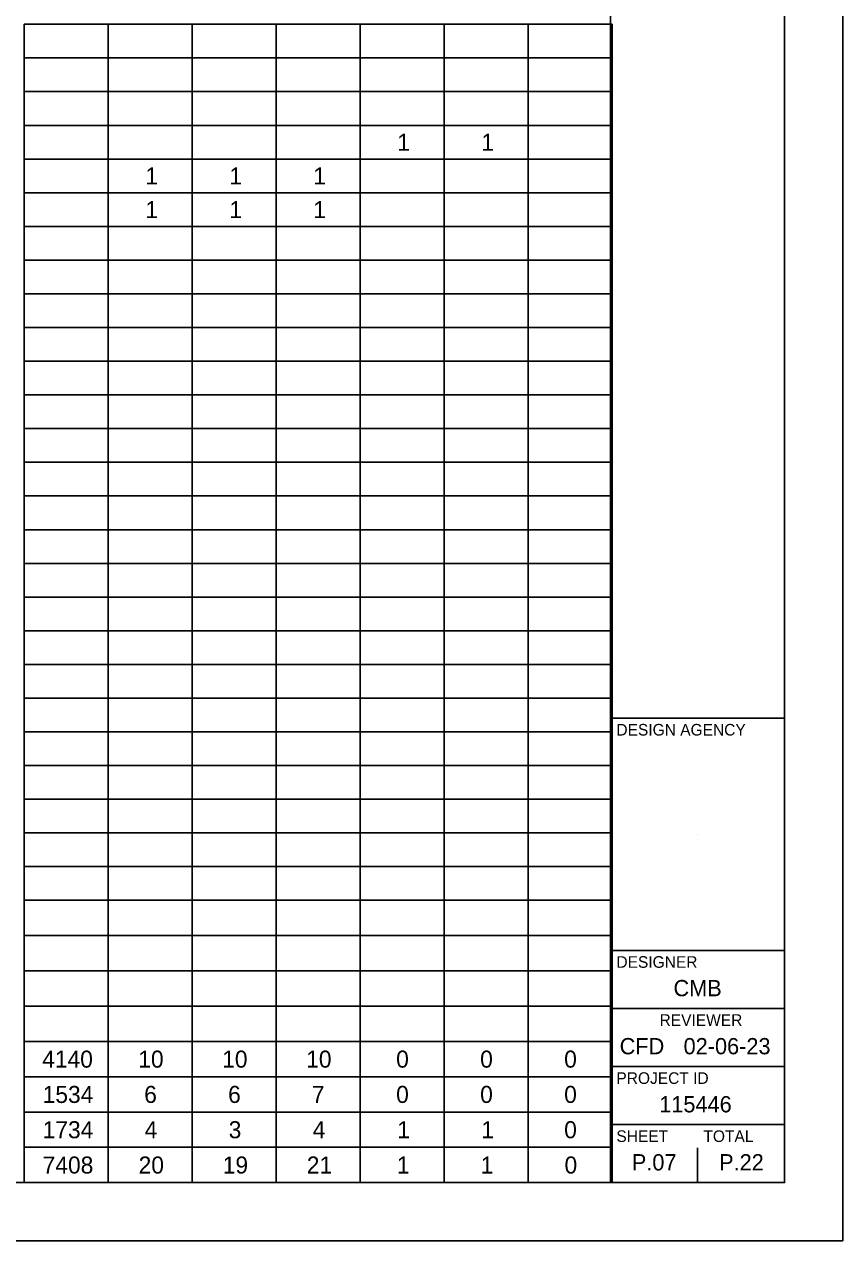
# Model space of a CAD drawing. Extents: x 0 to 34, y 0 to 22.
# Drawn here: x 26.95 to 34, y 0 to 10.47 of the extents above; entities that cross this region are included whole.
import ezdxf

# ---------------------------------------------------------------- set-up
doc = ezdxf.new("R2010")
doc.units = 0
for name, color, linetype in [('Default', 7, 'Continuous'), ('SH_Border', 7, 'Continuous'), ('SH_Cut_Line', 7, 'Continuous'), ('SH_Data', 7, 'Continuous')]:
    doc.layers.add(name, color=color, linetype=linetype)

msp = doc.modelspace()

# ---------------------------------------------------------------- linework, layer by layer
at = {"layer": 'Default'}
for p, q in [((26.948, 10.475), (27.671, 10.475)), ((26.948, 10.475), (26.948, 10.185)), ((27.671, 10.475), (29.842, 10.475)), ((27.671, 10.475), (27.671, 10.185)), ((28.395, 10.475), (28.395, 10.185)), ((29.119, 10.475), (29.119, 10.185)), ((29.842, 10.475), (30.566, 10.475)), ((29.842, 10.475), (29.842, 10.185)), ((30.566, 10.475), (31.289, 10.475)), ((30.566, 10.475), (30.566, 10.185)), ((31.289, 10.475), (32.013, 10.475)), ((31.289, 10.475), (31.289, 10.185)), ((32.013, 10.475), (32.013, 10.185)), ((26.948, 10.185), (27.671, 10.185)), ((26.948, 10.185), (26.948, 9.895)), ((27.671, 10.185), (29.842, 10.185)), ((27.671, 10.185), (27.671, 9.895)), ((28.395, 10.185), (28.395, 9.895)), ((29.119, 10.185), (29.119, 9.895)), ((29.842, 10.185), (30.566, 10.185)), ((29.842, 10.185), (29.842, 9.895)), ((30.566, 10.185), (31.289, 10.185)), ((30.566, 10.185), (30.566, 9.895)), ((31.289, 10.185), (32.013, 10.185)), ((31.289, 10.185), (31.289, 9.895)), ((32.013, 10.185), (32.013, 9.895)), ((26.948, 9.895), (27.671, 9.895)), ((26.948, 9.895), (26.948, 9.604)), ((27.671, 9.895), (29.842, 9.895)), ((27.671, 9.895), (27.671, 9.604)), ((28.395, 9.895), (28.395, 9.604)), ((29.119, 9.895), (29.119, 9.604)), ((29.842, 9.895), (30.566, 9.895)), ((29.842, 9.895), (29.842, 9.604)), ((30.566, 9.895), (31.289, 9.895)), ((30.566, 9.895), (30.566, 9.604)), ((31.289, 9.895), (32.013, 9.895)), ((31.289, 9.895), (31.289, 9.604)), ((32.013, 9.895), (32.013, 9.604)), ((26.948, 9.604), (27.671, 9.604)), ((26.948, 9.604), (26.948, 9.314)), ((27.671, 9.604), (29.842, 9.604)), ((27.671, 9.604), (27.671, 9.314)), ((28.395, 9.604), (28.395, 9.314)), ((29.119, 9.604), (29.119, 9.314)), ((29.842, 9.604), (30.566, 9.604)), ((29.842, 9.604), (29.842, 9.314)), ((30.566, 9.604), (31.289, 9.604)), ((30.566, 9.604), (30.566, 9.314)), ((31.289, 9.604), (32.013, 9.604)), ((31.289, 9.604), (31.289, 9.314)), ((32.013, 9.604), (32.013, 9.314)), ((26.948, 9.314), (27.671, 9.314)), ((26.948, 9.314), (26.948, 9.024)), ((27.671, 9.314), (29.842, 9.314)), ((27.671, 9.314), (27.671, 9.024)), ((28.395, 9.314), (28.395, 9.024)), ((29.119, 9.314), (29.119, 9.024)), ((29.842, 9.314), (30.566, 9.314)), ((29.842, 9.314), (29.842, 9.024)), ((30.566, 9.314), (31.289, 9.314)), ((30.566, 9.314), (30.566, 9.024)), ((31.289, 9.314), (32.013, 9.314)), ((31.289, 9.314), (31.289, 9.024)), ((32.013, 9.314), (32.013, 9.024)), ((26.948, 9.024), (27.671, 9.024)), ((26.948, 9.024), (26.948, 8.734)), ((27.671, 9.024), (29.842, 9.024)), ((27.671, 9.024), (27.671, 8.734)), ((28.395, 9.024), (28.395, 8.734)), ((29.119, 9.024), (29.119, 8.734)), ((29.842, 9.024), (30.566, 9.024)), ((29.842, 9.024), (29.842, 8.734)), ((30.566, 9.024), (31.289, 9.024)), ((30.566, 9.024), (30.566, 8.734)), ((31.289, 9.024), (32.013, 9.024)), ((31.289, 9.024), (31.289, 8.734)), ((32.013, 9.024), (32.013, 8.734)), ((26.948, 8.734), (27.671, 8.734)), ((26.948, 8.734), (26.948, 8.444)), ((27.671, 8.734), (29.842, 8.734)), ((27.671, 8.734), (27.671, 8.444)), ((28.395, 8.734), (28.395, 8.444)), ((29.119, 8.734), (29.119, 8.444)), ((29.842, 8.734), (30.566, 8.734)), ((29.842, 8.734), (29.842, 8.444)), ((30.566, 8.734), (31.289, 8.734)), ((30.566, 8.734), (30.566, 8.444)), ((31.289, 8.734), (32.013, 8.734)), ((31.289, 8.734), (31.289, 8.444)), ((32.013, 8.734), (32.013, 8.444)), ((26.948, 8.444), (27.671, 8.444)), ((26.948, 8.444), (26.948, 8.154)), ((27.671, 8.444), (29.842, 8.444)), ((27.671, 8.444), (27.671, 8.154)), ((28.395, 8.444), (28.395, 8.154)), ((29.119, 8.444), (29.119, 8.154)), ((29.842, 8.444), (30.566, 8.444)), ((29.842, 8.444), (29.842, 8.154)), ((30.566, 8.444), (31.289, 8.444)), ((30.566, 8.444), (30.566, 8.154)), ((31.289, 8.444), (32.013, 8.444)), ((31.289, 8.444), (31.289, 8.154)), ((32.013, 8.444), (32.013, 8.154)), ((26.948, 8.154), (27.671, 8.154)), ((26.948, 8.154), (26.948, 7.864)), ((27.671, 8.154), (29.842, 8.154)), ((27.671, 8.154), (27.671, 7.864)), ((28.395, 8.154), (28.395, 7.864)), ((29.119, 8.154), (29.119, 7.864)), ((29.842, 8.154), (30.566, 8.154)), ((29.842, 8.154), (29.842, 7.864)), ((30.566, 8.154), (31.289, 8.154)), ((30.566, 8.154), (30.566, 7.864)), ((31.289, 8.154), (32.013, 8.154)), ((31.289, 8.154), (31.289, 7.864)), ((32.013, 8.154), (32.013, 7.864)), ((26.948, 7.864), (27.671, 7.864)), ((26.948, 7.864), (26.948, 7.574)), ((27.671, 7.864), (29.842, 7.864)), ((27.671, 7.864), (27.671, 7.574)), ((28.395, 7.864), (28.395, 7.574)), ((29.119, 7.864), (29.119, 7.574)), ((29.842, 7.864), (30.566, 7.864)), ((29.842, 7.864), (29.842, 7.574)), ((30.566, 7.864), (31.289, 7.864)), ((30.566, 7.864), (30.566, 7.574)), ((31.289, 7.864), (32.013, 7.864)), ((31.289, 7.864), (31.289, 7.574)), ((32.013, 7.864), (32.013, 7.574)), ((26.948, 7.574), (27.671, 7.574)), ((26.948, 7.574), (26.948, 7.283)), ((27.671, 7.574), (29.842, 7.574)), ((27.671, 7.574), (27.671, 7.283)), ((28.395, 7.574), (28.395, 7.283)), ((29.119, 7.574), (29.119, 7.283)), ((29.842, 7.574), (30.566, 7.574)), ((29.842, 7.574), (29.842, 7.283)), ((30.566, 7.574), (31.289, 7.574)), ((30.566, 7.574), (30.566, 7.283)), ((31.289, 7.574), (32.013, 7.574)), ((31.289, 7.574), (31.289, 7.283)), ((32.013, 7.574), (32.013, 7.283)), ((26.948, 7.283), (27.671, 7.283)), ((26.948, 7.283), (26.948, 6.993)), ((27.671, 7.283), (29.842, 7.283)), ((27.671, 7.283), (27.671, 6.993)), ((28.395, 7.283), (28.395, 6.993)), ((29.119, 7.283), (29.119, 6.993)), ((29.842, 7.283), (30.566, 7.283)), ((29.842, 7.283), (29.842, 6.993)), ((30.566, 7.283), (31.289, 7.283)), ((30.566, 7.283), (30.566, 6.993)), ((31.289, 7.283), (32.013, 7.283)), ((31.289, 7.283), (31.289, 6.993)), ((32.013, 7.283), (32.013, 6.993)), ((26.948, 6.993), (27.671, 6.993)), ((26.948, 6.993), (26.948, 6.703)), ((27.671, 6.993), (29.842, 6.993)), ((27.671, 6.993), (27.671, 6.703)), ((28.395, 6.993), (28.395, 6.703)), ((29.119, 6.993), (29.119, 6.703)), ((29.842, 6.993), (30.566, 6.993)), ((29.842, 6.993), (29.842, 6.703)), ((30.566, 6.993), (31.289, 6.993)), ((30.566, 6.993), (30.566, 6.703)), ((31.289, 6.993), (32.013, 6.993)), ((31.289, 6.993), (31.289, 6.703)), ((32.013, 6.993), (32.013, 6.703)), ((26.948, 6.703), (27.671, 6.703)), ((26.948, 6.703), (26.948, 6.413)), ((27.671, 6.703), (29.842, 6.703)), ((27.671, 6.703), (27.671, 6.413)), ((28.395, 6.703), (28.395, 6.413)), ((29.119, 6.703), (29.119, 6.413)), ((29.842, 6.703), (30.566, 6.703)), ((29.842, 6.703), (29.842, 6.413)), ((30.566, 6.703), (31.289, 6.703)), ((30.566, 6.703), (30.566, 6.413)), ((31.289, 6.703), (32.013, 6.703)), ((31.289, 6.703), (31.289, 6.413)), ((32.013, 6.703), (32.013, 6.413)), ((26.948, 6.413), (27.671, 6.413)), ((26.948, 6.413), (26.948, 6.123)), ((27.671, 6.413), (29.842, 6.413)), ((27.671, 6.413), (27.671, 6.123)), ((28.395, 6.413), (28.395, 6.123)), ((29.119, 6.413), (29.119, 6.123)), ((29.842, 6.413), (30.566, 6.413)), ((29.842, 6.413), (29.842, 6.123)), ((30.566, 6.413), (31.289, 6.413)), ((30.566, 6.413), (30.566, 6.123)), ((31.289, 6.413), (32.013, 6.413)), ((31.289, 6.413), (31.289, 6.123)), ((32.013, 6.413), (32.013, 6.123)), ((26.948, 6.123), (27.671, 6.123)), ((26.948, 6.123), (26.948, 5.833)), ((27.671, 6.123), (29.842, 6.123)), ((27.671, 6.123), (27.671, 5.833)), ((28.395, 6.123), (28.395, 5.833)), ((29.119, 6.123), (29.119, 5.833)), ((29.842, 6.123), (30.566, 6.123)), ((29.842, 6.123), (29.842, 5.833)), ((30.566, 6.123), (31.289, 6.123)), ((30.566, 6.123), (30.566, 5.833)), ((31.289, 6.123), (32.013, 6.123)), ((31.289, 6.123), (31.289, 5.833)), ((32.013, 6.123), (32.013, 5.833)), ((26.948, 5.833), (27.671, 5.833)), ((26.948, 5.833), (26.948, 5.543)), ((27.671, 5.833), (29.842, 5.833)), ((27.671, 5.833), (27.671, 5.543)), ((28.395, 5.833), (28.395, 5.543)), ((29.119, 5.833), (29.119, 5.543)), ((29.842, 5.833), (30.566, 5.833)), ((29.842, 5.833), (29.842, 5.543)), ((30.566, 5.833), (31.289, 5.833)), ((30.566, 5.833), (30.566, 5.543)), ((31.289, 5.833), (32.013, 5.833)), ((31.289, 5.833), (31.289, 5.543)), ((32.013, 5.833), (32.013, 5.543)), ((26.948, 5.543), (27.671, 5.543)), ((26.948, 5.543), (26.948, 5.252)), ((27.671, 5.543), (29.842, 5.543)), ((27.671, 5.543), (27.671, 5.252)), ((28.395, 5.543), (28.395, 5.252)), ((29.119, 5.543), (29.119, 5.252)), ((29.842, 5.543), (30.566, 5.543)), ((29.842, 5.543), (29.842, 5.252)), ((30.566, 5.543), (31.289, 5.543)), ((30.566, 5.543), (30.566, 5.252)), ((31.289, 5.543), (32.013, 5.543)), ((31.289, 5.543), (31.289, 5.252)), ((32.013, 5.543), (32.013, 5.252)), ((26.948, 5.252), (27.671, 5.252)), ((26.948, 5.252), (26.948, 4.672)), ((27.671, 5.252), (29.842, 5.252)), ((27.671, 5.252), (27.671, 4.672)), ((28.395, 5.252), (28.395, 4.672)), ((29.119, 5.252), (29.119, 4.672)), ((29.842, 5.252), (30.566, 5.252)), ((29.842, 5.252), (29.842, 4.672)), ((30.566, 5.252), (31.289, 5.252)), ((30.566, 5.252), (30.566, 4.672)), ((31.289, 5.252), (32.013, 5.252)), ((31.289, 5.252), (31.289, 4.672)), ((32.013, 5.252), (32.013, 4.672)), ((26.948, 4.962), (27.671, 4.962)), ((27.671, 4.962), (29.842, 4.962)), ((29.842, 4.962), (30.566, 4.962)), ((30.566, 4.962), (31.289, 4.962)), ((31.289, 4.962), (32.013, 4.962)), ((26.948, 4.672), (27.671, 4.672)), ((26.948, 4.672), (26.948, 4.092)), ((27.671, 4.672), (29.842, 4.672)), ((27.671, 4.672), (27.671, 4.092)), ((28.395, 4.672), (28.395, 4.092)), ((29.119, 4.672), (29.119, 4.092)), ((29.842, 4.672), (30.566, 4.672)), ((29.842, 4.672), (29.842, 4.092)), ((30.566, 4.672), (31.289, 4.672)), ((30.566, 4.672), (30.566, 4.092)), ((31.289, 4.672), (32.013, 4.672)), ((31.289, 4.672), (31.289, 4.092)), ((32.013, 4.672), (32.013, 4.092)), ((26.948, 4.382), (27.671, 4.382)), ((27.671, 4.382), (29.842, 4.382)), ((29.842, 4.382), (30.566, 4.382)), ((30.566, 4.382), (31.289, 4.382)), ((31.289, 4.382), (32.013, 4.382)), ((26.948, 4.092), (27.671, 4.092)), ((26.948, 4.092), (26.948, 3.802)), ((27.671, 4.092), (29.842, 4.092)), ((27.671, 4.092), (27.671, 3.802)), ((28.395, 4.092), (28.395, 3.802)), ((29.119, 4.092), (29.119, 3.802)), ((29.842, 4.092), (30.566, 4.092)), ((29.842, 4.092), (29.842, 3.802)), ((30.566, 4.092), (31.289, 4.092)), ((30.566, 4.092), (30.566, 3.802)), ((31.289, 4.092), (32.013, 4.092)), ((31.289, 4.092), (31.289, 3.802)), ((32.013, 4.092), (32.013, 3.802)), ((26.948, 3.802), (27.671, 3.802)), ((26.948, 3.802), (26.948, 3.222)), ((27.671, 3.802), (29.842, 3.802)), ((27.671, 3.802), (27.671, 3.222)), ((28.395, 3.802), (28.395, 3.222)), ((29.119, 3.802), (29.119, 3.222)), ((29.842, 3.802), (30.566, 3.802)), ((29.842, 3.802), (29.842, 3.222)), ((30.566, 3.802), (31.289, 3.802)), ((30.566, 3.802), (30.566, 3.222)), ((31.289, 3.802), (32.013, 3.802)), ((31.289, 3.802), (31.289, 3.222)), ((32.013, 3.802), (32.013, 3.222)), ((26.948, 3.512), (27.671, 3.512)), ((27.671, 3.512), (29.842, 3.512)), ((29.842, 3.512), (30.566, 3.512)), ((30.566, 3.512), (31.289, 3.512)), ((31.289, 3.512), (32.013, 3.512)), ((26.948, 3.222), (27.671, 3.222)), ((26.948, 3.222), (26.948, 2.627)), ((27.671, 3.222), (29.842, 3.222)), ((27.671, 3.222), (27.671, 2.627)), ((28.395, 3.222), (28.395, 2.627)), ((29.119, 3.222), (29.119, 2.627)), ((29.842, 3.222), (30.566, 3.222)), ((29.842, 3.222), (29.842, 2.627)), ((30.566, 3.222), (31.289, 3.222)), ((30.566, 3.222), (30.566, 2.627)), ((31.289, 3.222), (32.013, 3.222)), ((31.289, 3.222), (31.289, 2.627)), ((32.013, 3.222), (32.013, 2.627)), ((26.948, 2.931), (27.671, 2.931)), ((27.671, 2.931), (29.842, 2.931)), ((29.842, 2.931), (30.566, 2.931)), ((30.566, 2.931), (31.289, 2.931)), ((31.289, 2.931), (32.013, 2.931)), ((26.948, 2.627), (27.671, 2.627)), ((26.948, 2.627), (26.948, 2.323)), ((27.671, 2.627), (29.842, 2.627)), ((27.671, 2.627), (27.671, 2.323)), ((28.395, 2.627), (28.395, 2.323)), ((29.119, 2.627), (29.119, 2.323)), ((29.842, 2.627), (30.566, 2.627)), ((29.842, 2.627), (29.842, 2.323)), ((30.566, 2.627), (31.289, 2.627)), ((30.566, 2.627), (30.566, 2.323)), ((31.289, 2.627), (32.013, 2.627)), ((31.289, 2.627), (31.289, 2.323)), ((32.013, 2.627), (32.013, 2.323)), ((26.948, 2.323), (27.671, 2.323)), ((26.948, 2.323), (26.948, 2.02)), ((27.671, 2.323), (29.842, 2.323)), ((27.671, 2.323), (27.671, 2.02)), ((28.395, 2.323), (28.395, 2.02)), ((29.119, 2.323), (29.119, 2.02)), ((29.842, 2.323), (30.566, 2.323)), ((29.842, 2.323), (29.842, 2.02)), ((30.566, 2.323), (31.289, 2.323)), ((30.566, 2.323), (30.566, 2.02)), ((31.289, 2.323), (32.013, 2.323)), ((31.289, 2.323), (31.289, 2.02)), ((32.013, 2.323), (32.013, 2.02)), ((26.948, 2.02), (27.671, 2.02)), ((26.948, 2.02), (26.948, 1.716)), ((27.671, 2.02), (29.842, 2.02)), ((27.671, 2.02), (27.671, 1.716)), ((28.395, 2.02), (28.395, 1.716)), ((29.119, 2.02), (29.119, 1.716)), ((29.842, 2.02), (30.566, 2.02)), ((29.842, 2.02), (29.842, 1.716)), ((30.566, 2.02), (31.289, 2.02)), ((30.566, 2.02), (30.566, 1.716)), ((31.289, 2.02), (32.013, 2.02)), ((31.289, 2.02), (31.289, 1.716)), ((32.013, 2.02), (32.013, 1.716)), ((26.948, 1.716), (27.671, 1.716)), ((26.948, 1.716), (26.948, 1.412)), ((27.671, 1.716), (29.842, 1.716)), ((27.671, 1.716), (27.671, 1.412)), ((28.395, 1.716), (28.395, 1.412)), ((29.119, 1.716), (29.119, 1.412)), ((29.842, 1.716), (30.566, 1.716)), ((29.842, 1.716), (29.842, 1.412)), ((30.566, 1.716), (31.289, 1.716)), ((30.566, 1.716), (30.566, 1.412)), ((31.289, 1.716), (32.013, 1.716)), ((31.289, 1.716), (31.289, 1.412)), ((32.013, 1.716), (32.013, 1.412)), ((26.948, 1.412), (27.671, 1.412)), ((26.948, 1.412), (26.948, 1.108)), ((27.671, 1.412), (29.842, 1.412)), ((27.671, 1.412), (27.671, 1.108)), ((28.395, 1.412), (28.395, 1.108)), ((29.119, 1.412), (29.119, 1.108)), ((29.842, 1.412), (30.566, 1.412)), ((29.842, 1.412), (29.842, 1.108)), ((30.566, 1.412), (31.289, 1.412)), ((30.566, 1.412), (30.566, 1.108)), ((31.289, 1.412), (32.013, 1.412)), ((31.289, 1.412), (31.289, 1.108)), ((32.013, 1.412), (32.013, 1.108)), ((26.948, 1.108), (27.671, 1.108)), ((26.948, 1.108), (26.948, 0.804)), ((27.671, 1.108), (29.842, 1.108)), ((27.671, 1.108), (27.671, 0.804)), ((28.395, 1.108), (28.395, 0.804)), ((29.119, 1.108), (29.119, 0.804)), ((29.842, 1.108), (30.566, 1.108)), ((29.842, 1.108), (29.842, 0.804)), ((30.566, 1.108), (31.289, 1.108)), ((30.566, 1.108), (30.566, 0.804)), ((31.289, 1.108), (32.013, 1.108)), ((31.289, 1.108), (31.289, 0.804)), ((32.013, 1.108), (32.013, 0.804)), ((26.948, 0.804), (27.671, 0.804)), ((26.948, 0.804), (26.948, 0.5)), ((27.671, 0.804), (29.842, 0.804)), ((27.671, 0.804), (27.671, 0.5)), ((28.395, 0.804), (28.395, 0.5)), ((29.119, 0.804), (29.119, 0.5)), ((29.842, 0.804), (30.566, 0.804)), ((29.842, 0.804), (29.842, 0.5)), ((30.566, 0.804), (31.289, 0.804)), ((30.566, 0.804), (30.566, 0.5)), ((31.289, 0.804), (32.013, 0.804)), ((31.289, 0.804), (31.289, 0.5)), ((32.013, 0.804), (32.013, 0.5)), ((26.948, 0.5), (27.671, 0.5)), ((27.671, 0.5), (29.842, 0.5)), ((29.842, 0.5), (30.566, 0.5)), ((30.566, 0.5), (31.289, 0.5)), ((31.289, 0.5), (32.013, 0.5))]:
    msp.add_line(p, q, dxfattribs=at)
at = {"layer": 'SH_Border'}
for p, q in [((32, 0.5), (32, 21.5)), ((32, 4.5), (33.5, 4.5)), ((32, 2.5), (33.5, 2.5)), ((32, 2), (33.5, 2)), ((32, 1.5), (33.5, 1.5)), ((32, 1), (33.5, 1))]:
    msp.add_line(p, q, dxfattribs=at)
msp.add_lwpolyline([(1.5, 21.5), (33.5, 21.5), (33.5, 0.5), (1.5, 0.5)], close=True, dxfattribs=at)
at = {"layer": 'SH_Cut_Line'}
msp.add_lwpolyline([(0, 0), (34, 0), (34, 22), (0, 22)], close=True, dxfattribs=at)
at = {"layer": 'SH_Data'}
for p, q in [((32.75, 3.5), (32.75, 3.5)), ((32.75, 0.5), (32.75, 0.8)), ((32.375, 0.675), (32.375, 0.675))]:
    msp.add_line(p, q, dxfattribs=at)

# ---------------------------------------------------------------- texts
at = {"layer": 'Default'}
for s, height, p in [('1', 0.147, (30.162, 9.386)), ('1', 0.147, (30.886, 9.386)), ('1', 0.147, (27.991, 9.096)), ('1', 0.147, (28.715, 9.096)), ('1', 0.147, (29.438, 9.096)), ('1', 0.147, (27.991, 8.806)), ('1', 0.147, (28.715, 8.806)), ('1', 0.147, (29.438, 8.806)), ('4140', 0.1468, (27.102, 1.49)), ('10', 0.1468, (27.93, 1.49)), ('10', 0.1468, (28.653, 1.49)), ('10', 0.1468, (29.377, 1.49)), ('0', 0.147, (30.152, 1.49)), ('0', 0.147, (30.876, 1.49)), ('0', 0.147, (31.6, 1.49)), ('1534', 0.1468, (27.106, 1.186)), ('6', 0.147, (27.981, 1.186)), ('6', 0.147, (28.704, 1.186)), ('7', 0.147, (29.426, 1.186)), ('0', 0.147, (30.152, 1.186)), ('0', 0.147, (30.876, 1.186)), ('0', 0.147, (31.6, 1.186)), ('1734', 0.1468, (27.106, 0.882)), ('4', 0.147, (27.985, 0.882)), ('3', 0.147, (28.709, 0.882)), ('4', 0.147, (29.433, 0.882)), ('1', 0.147, (30.162, 0.882)), ('1', 0.147, (30.886, 0.882)), ('0', 0.147, (31.6, 0.882)), ('7408', 0.1468, (27.106, 0.578)), ('20', 0.1468, (27.933, 0.578)), ('19', 0.1468, (28.658, 0.578)), ('21', 0.1468, (29.382, 0.578)), ('1', 0.147, (30.158, 0.578)), ('1', 0.147, (30.881, 0.578)), ('0', 0.147, (31.603, 0.578))]:
    msp.add_text(s, height=height, dxfattribs=at).set_placement(p)
at = {"layer": 'SH_Data'}
for s, height, p in [('DESIGN AGENCY', 0.1, (32.05, 4.35)), ('DESIGNER', 0.1, (32.05, 2.35)), ('CMB', 0.14, (32.542, 2.105)), ('REVIEWER', 0.1, (32.422, 1.85)), ('CFD', 0.14, (32.078, 1.605)), ('02-06-23', 0.14, (32.629, 1.605)), ('PROJECT ID', 0.1, (32.05, 1.35)), ('115446', 0.14, (32.419, 1.105)), ('SHEET', 0.1, (32.05, 0.85)), ('TOTAL', 0.1, (32.8, 0.85)), ('P.07', 0.14, (32.183, 0.605)), ('P.22', 0.14, (32.935, 0.605))]:
    msp.add_text(s, height=height, dxfattribs=at).set_placement(p)

doc.saveas('drawing.dxf')
